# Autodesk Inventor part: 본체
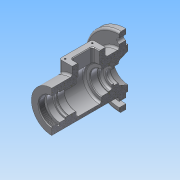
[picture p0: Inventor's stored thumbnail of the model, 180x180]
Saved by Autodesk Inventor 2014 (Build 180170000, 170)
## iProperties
Created: 2017-05
Part Number: 본체
Material: 알루미늄 6061
Document SubType Name: Modeling
Designer: SCD-A14
Density: 2.71 g/cm^3
Appearance: 알루미늄 - 평지
Mass: 682.14 g
Surface Area: 618.19 cm^2
Volume: 251.712 cm^3
Author: SCD-A14
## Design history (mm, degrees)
sketch "스케치1"
  geometry: C1 r 31 at (0, 0); 1 further point
  constraints: 1 centre point, 1 coincident
  dimensions: "d0" = 62 diameter of C1
extrude "돌출1" new body sketch "스케치1" distance "d1" = 115; taper "d2" = 0 deg
sketch "스케치2"
  geometry: 2 further points
  constraints: 1 coincident
hole "구멍1" sketch "스케치2" at (0, 0) diameter "d3" = 40.376; stored, may be unused: countersink angle "d7" = 90 deg, drill point angle "d9" = 0 deg; dims "d4" = 6, "d5" = 4, "d6" = 2, "d8" = 9
sketch "스케치3"
  geometry: C1 r 24 at (0, 0); 1 further point
  constraints: 1 centre point, 1 coincident
  dimensions: "d10" = 48 diameter of C1
extrude "돌출2" cut sketch "스케치3" distance "d11" = 3; taper "d12" = 0 deg
sketch "스케치4"
  geometry: C1 r 20 at (0, 0); 1 further point
  constraints: 1 centre point, 1 coincident
  dimensions: "d13" = 40 diameter of C1
extrude "돌출3" cut sketch "스케치4" distance "d14" = 9; taper "d15" = 0 deg
node "작업 평면1"
sketch "스케치5"
  geometry: C1 r 18.5 at (0, 0); 1 further point
  constraints: 1 centre point, 1 coincident
  dimensions: "d17" = 37 diameter of C1
extrude "돌출4" cut sketch "스케치5" distance "d18" = 1.75; taper "d19" = 0 deg
sketch "스케치6"
  geometry: C1 r 17.5 at (0, 0); 1 further point
  constraints: 1 centre point, 1 coincident
  dimensions: "d20" = 35 diameter of C1
extrude "돌출5" cut sketch "스케치6" distance "d21" = 65; taper "d22" = 0 deg
sketch "스케치7"
  geometry: L1 (-31, -115)-(31, -115) reference; L2 (-31, 0)-(31, 0) reference; L3 (0, -115)-(22, -115); L4 (-31, -115)-(31, -115) reference; L5 (0, -115)-(0, -101); L6 (0, -101)-(16, -101); L7 (16, -101)-(22, -115); 1 further point
  constraints: 8 end point, 2 perpendicular, 1 midpoint, 1 point on line
  dimensions: "d23" = 22 distance of L3.start L3.end; "d24" = 14 distance of L3.start L5.end; "d25" = 16 distance of L5.end L6.end
revolve "회전1" sketch "스케치7" stored, may be unused: angle "d26" = 90 deg
sketch "스케치8"
  geometry: C1 r 12.5 at (0, 0); 1 further point
  constraints: 1 centre point, 1 coincident
  dimensions: "d27" = 25 diameter of C1
extrude "돌출6" cut sketch "스케치8" distance "d28" = 7.3; taper "d29" = 0 deg
sketch "스케치9"
  geometry: C1 r 10 at (0, 0); 1 further point
  constraints: 1 centre point, 1 coincident
  dimensions: "d30" = 20 diameter of C1
extrude "돌출7" cut sketch "스케치9" distance "d31" = 2.7; taper "d32" = 0 deg
sketch "스케치10"
  geometry: C1 r 16.5 at (0, 0); 1 further point
  constraints: 1 centre point, 1 coincident
  dimensions: "d33" = 33 diameter of C1
extrude "돌출8" cut sketch "스케치10" distance "d34" = 5; taper "d35" = 0 deg
node "작업 평면2"
sketch "스케치11"
  geometry: C1 r 26 at (0, 0); 1 further point
  constraints: 1 centre point, 1 coincident
  dimensions: "d37" = 52 diameter of C1
extrude "돌출9" cut sketch "스케치11" distance "d38" = 38; taper "d39" = 0 deg
node "작업 평면3"
sketch "스케치12"
  geometry: C1 r 53 at (0, 0); 1 further point
  constraints: 1 centre point, 1 coincident
  dimensions: "d41" = 106 diameter of C1
extrude "돌출10" join sketch "스케치12" distance "d42" = 13; taper "d43" = 0 deg
sketch "스케치15"
  geometry: A1 r 45.5 centre (0, 0) between (45.5, 0) and (0, 45.5); A2 r 4 centre (0, 41.5) between (0, 45.5) and (0, 37.5); A3 r 37.5 centre (0, 0) between (37.5, 0) and (0, 37.5); A4 r 4 centre (41.5, 0) between (37.5, 0) and (45.5, 0); 1 further point
  constraints: 8 point on circle, 4 centre point, 1 coincident, 1 horizontal alignment, 1 vertical alignment
  dimensions: "d109" = 37.5 radius of A3; "d110" = 45.5 radius of A1; "d111" = 4 radius of A2; "d112" = 4 radius of A4; "d113" = 41.5 distance of point (0, 0) A4.centre; "d114" = 41.5 distance of A2.centre point (0, 0)
extrude "돌출11" cut sketch "스케치15" stored distance "d57" = 13; taper "d58" = 0 deg
node "작업 평면4"
sketch "스케치16"
  geometry: L1 (20, -31)-(-20, -31); L2 (-20, -31)-(-20, -81); L3 (-20, -81)-(20, -81); L4 (20, -81)-(20, -31); L5 (20, -31)-(-20, -81); L6 (-20, -31)-(20, -81); 2 further points
  constraints: 12 end point, 2 midpoint, 2 parallel, 1 horizontal, 1 perpendicular
  dimensions: "d64" = 56 distance of point (0, 0) point (0, -56); "d65" = 50 distance between parallel lines of L3 L1; "d66" = 40 distance between parallel lines of L4 L2; "d67" = 0 horizontal distance of point (0, 0) point (0, -56)
extrude "돌출12" join sketch "스케치16" stored distance "d68" = 10; taper "d69" = 0 deg
sketch "스케치17"
  geometry: L1 (-31, 99)-(31, 99) reference; L2 (31, 0)-(-31, 0) reference; L3 (20, 81)-(20, 31) reference; L4 (20, 31)-(-20, 31) reference; L5 (-20, 31)-(-20, 81) reference; L6 (-20, 81)-(20, 81) reference; L7 (-11, 40)-(11, 40); L8 (11, 40)-(11, 72); L9 (11, 72)-(-11, 72); L10 (-11, 72)-(-11, 40); 5 further points
  constraints: 8 end point, 4 midpoint, 2 parallel, 1 horizontal, 1 horizontal alignment, 1 perpendicular, 1 vertical alignment
  dimensions: "d70" = 22 distance between parallel lines of L10 L8; "d71" = 32 distance between parallel lines of L9 L7
extrude "돌출13" cut sketch "스케치17" distance "d72" = 38.75; taper "d73" = 0 deg
sketch "스케치18"
  geometry: L1 (-31, 99)-(31, 99) reference; L2 (31, 0)-(-31, 0) reference; L3 (20, 81)-(20, 31) reference; L4 (20, 31)-(-20, 31) reference; L5 (-20, 31)-(-20, 81) reference; L6 (-20, 81)-(20, 81) reference; L7 (-15.5, 35.5)-(15.5, 35.5); L8 (15.5, 35.5)-(15.5, 76.5); L9 (15.5, 76.5)-(-15.5, 76.5); L10 (-15.5, 76.5)-(-15.5, 35.5); 9 further points
  constraints: 8 end point, 4 coincident, 4 midpoint, 2 parallel, 1 horizontal, 1 horizontal alignment, 1 perpendicular, 1 vertical alignment
  dimensions: "d74" = 41 distance of L9.end L7.start; "d75" = 31 distance of L7.start L7.end
hole "구멍2" sketch "스케치18" at (-15.5, 35.5), (-15.5, 76.5), (15.5, 76.5), (15.5, 35.5) diameter "d76" = 2.459; stored, may be unused: countersink angle "d80" = 90 deg, drill point angle "d82" = 118 deg; dims "d77" = 6, "d78" = 4, "d79" = 2, "d81" = 8
sketch "스케치19"
  geometry: L1 (68, -13)-(68, -75) reference; L2 (-31, -75)-(-31, -13) reference; L3 (50, -20.315)-(0, -20.315) reference; L4 (0, -20.315)-(0, -20.315) reference; L5 (0, -20.315)-(50, -20.315) reference; L6 (50, -20.315)-(50, -20.315) reference; L7 (0, -20.315)-(50, -20.315) reference; L8 (0, 0)-(0, -20.315) reference; L9 (50, 0)-(0, 0) reference; L10 (50, 0)-(50, -20.315) reference; 2 further points
  constraints: 1 other
  dimensions: "d83" = 56 distance from line of point (25, -8) L2; "d84" = 8 distance from line of L9 point (25, -8)
extrude "돌출14" join sketch "스케치19" distance "d85" = 0.5; taper "d86" = 0 deg
revolve "회전2" stored, may be unused: angle "d88" = 90 deg
fillet "모깎기1" dims "d89" = 3
chamfer "모따기1" distance "d90" = 1; stored, may be unused: second distance "d91" = 2, angle "d92" = 30 deg
fillet "모깎기2" dims "d93" = 3
chamfer "모따기2" distance "d94" = 1; stored, may be unused: second distance "d95" = 2, angle "d96" = 30 deg
fillet "모깎기3" dims "d97" = 3
chamfer "모따기3" distance "d98" = 1; stored, may be unused: second distance "d99" = 2, angle "d100" = 30 deg
fillet "모깎기4" dims "d101" = 0.3
fillet "모깎기5" dims "d102" = 3
fillet "모깎기6" dims "d103" = 3
fillet "모깎기7" dims "d104" = 3
chamfer "모따기4" distance "d105" = 1; stored, may be unused: second distance "d106" = 2, angle "d107" = 30 deg
fillet "모깎기8" dims "d108" = 3
sketch "스케치21"
  geometry: C1 r 53 at (0, 0); C2 r 31 at (0, 0); 1 further point
  constraints: 2 centre point, 2 coincident
  dimensions: "d115" = 106 diameter of C1; "d116" = 62 diameter of C2
extrude "돌출15" cut sketch "스케치21" distance "d117" = 3; taper "d118" = 0 deg
fillet "모깎기9" dims "d119" = 3
fillet "모깎기10" dims "d120" = 3
sketch "스케치22"
  geometry: L1 (22, -115)-(-22, -115) reference; L2 (0, -115)-(0, -101); L3 (0, -102)-(0, -112) reference; L4 (0, -101)-(16, -101); L5 (0, -115)-(22, -115); L6 (16, -101)-(22, -115); 1 further point
  constraints: 8 end point, 1 collinear, 1 midpoint, 1 perpendicular, 1 point on line
  dimensions: "d123" = 14 distance of L2.start L2.end; "d124" = 16 distance of L2.end L4.end; "d125" = 22 distance of L2.start L5.end
revolve "회전3" sketch "스케치22" stored, may be unused: angle "d126" = 90 deg
sketch "스케치23"
  geometry: C1 r 12.5 at (0, 0); 1 further point
  constraints: 1 centre point, 1 coincident
  dimensions: "d127" = 25 diameter of C1
extrude "돌출16" cut sketch "스케치23" stored distance "d128" = 3; taper "d129" = 0 deg
fillet "모깎기11" dims "d130" = 3
chamfer "모따기5" distance "d131" = 1; stored, may be unused: second distance "d132" = 2, angle "d133" = 30 deg
fillet "모깎기12" dims "d134" = 0.3
node "솔리드1"
pattern_circular "원형 패턴1" dims angle "d60" = 360 deg
node "투영된 루프1"
node "투영된 루프2"
node "투영된 루프3"
node "투영된 루프4"
node "투영된 루프5"
sketch "스케치20"
  geometry: L1 (22, -115)-(-22, -115) reference; L2 (31, -99)-(-31, -99) reference; L3 (-31, 0)-(31, 0) reference; L4 (23.685, -81)-(23.685, -31) reference; L5 (23.685, -31)-(23.685, -31) reference; L6 (23.685, -31)-(23.685, -81) reference; L7 (23.685, -81)-(23.685, -81) reference; L8 (31, -99)-(-31, -99) reference; L9 (16, -101)-(22, -115); L10 (0, -115)-(22, -115); L11 (0, -115)-(0, -101); L12 (0, -101)-(16, -101); 3 further points
  constraints: 8 end point, 2 midpoint, 2 perpendicular, 1 collinear, 1 point on line
  dimensions: "d121" = 14 distance of L10.start L11.end; "d122" = 16 distance of L11.end L9.start
node "투영된 루프6"
other parameters: "d16" = -26, "d36" = -37, "d40" = -16, "d62" = 44
